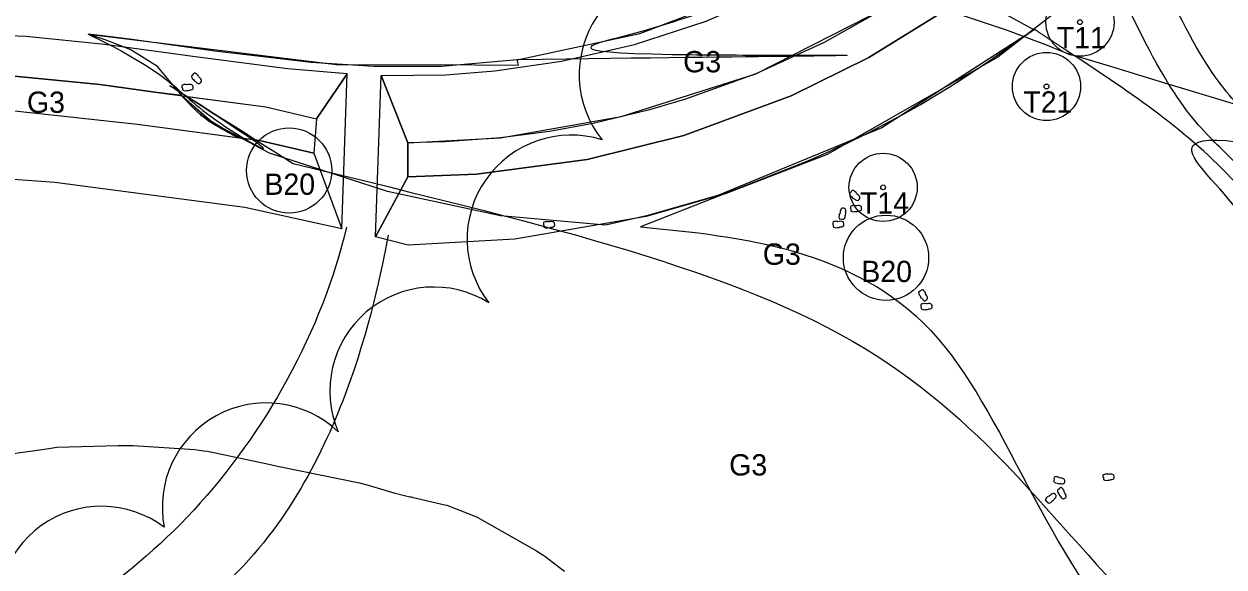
# Model space of a CAD drawing. Extents: x 0 to 512122, y 0 to 6212554.
# Drawn here: x 511431.1 to 511501.5, y 6211428.9 to 6211460.8 of the extents above; entities that cross this region are included whole.
import ezdxf

# ---------------------------------------------------------------- set-up
doc = ezdxf.new("R2010")
doc.units = 0
for name, color, linetype in [('_Marksten', 7, 'Continuous'), ('_Paths', 7, 'Continuous'), ('_Spredmingskorridor', 7, 'Continuous'), ('_Spredmingskorridor_hatch', 7, 'Continuous'), ('Clouds', 7, 'Continuous'), ('L40 jord udlagt muld og grøft', 7, 'Continuous'), ('Skel', 7, 'Continuous'), ('TV_U_AFM_Symbl_Gul', 7, 'Continuous'), ('TV_U_LYS_Mastenummer', 7, 'Continuous'), ('TV_U_LYS_Nyx330-Trafiksti-x2', 7, 'Continuous')]:
    doc.layers.add(name, color=color, linetype=linetype)

# ---------------------------------------------------------------- blocks, each defined once
blk = doc.blocks.new('SOLITAIRE TREES')
at = {"layer": 'Skel'}
for radius in [2, 0.141]:
    blk.add_circle((0, 0), radius, dxfattribs=at)

msp = doc.modelspace()

# ---------------------------------------------------------------- linework, layer by layer
at = {"layer": '_Marksten'}
for points in [[(511440.954, 6211457.714), (511440.981, 6211457.618), (511441.003, 6211457.563), (511441.071, 6211457.512), (511441.11, 6211457.459), (511441.148, 6211457.407), (511441.194, 6211457.399), (511441.225, 6211457.365), (511441.267, 6211457.32), (511441.316, 6211457.292), (511441.393, 6211457.268), (511441.425, 6211457.279), (511441.447, 6211457.297), (511441.481, 6211457.325), (511441.529, 6211457.384), (511441.54, 6211457.432), (511441.533, 6211457.465), (511441.514, 6211457.515), (511441.476, 6211457.575), (511441.418, 6211457.625), (511441.365, 6211457.681), (511441.346, 6211457.749), (511441.294, 6211457.784), (511441.267, 6211457.824), (511441.237, 6211457.852), (511441.17, 6211457.893), (511441.126, 6211457.884), (511441.058, 6211457.831), (511441.033, 6211457.774)], [(511440.419, 6211456.9), (511440.511, 6211456.862), (511440.569, 6211456.845), (511440.651, 6211456.868), (511440.716, 6211456.866), (511440.781, 6211456.864), (511440.815, 6211456.894), (511440.861, 6211456.898), (511440.923, 6211456.903), (511440.975, 6211456.925), (511441.04, 6211456.971), (511441.052, 6211457.003), (511441.052, 6211457.031), (511441.05, 6211457.076), (511441.034, 6211457.15), (511441.002, 6211457.188), (511440.972, 6211457.203), (511440.921, 6211457.218), (511440.85, 6211457.226), (511440.775, 6211457.211), (511440.698, 6211457.203), (511440.633, 6211457.23), (511440.573, 6211457.211), (511440.525, 6211457.213), (511440.485, 6211457.208), (511440.411, 6211457.18), (511440.392, 6211457.14), (511440.392, 6211457.054), (511440.421, 6211456.998)], [(511479.559, 6211450.815), (511479.594, 6211450.722), (511479.622, 6211450.669), (511479.695, 6211450.624), (511479.738, 6211450.576), (511479.781, 6211450.527), (511479.827, 6211450.524), (511479.862, 6211450.493), (511479.908, 6211450.452), (511479.959, 6211450.429), (511480.038, 6211450.413), (511480.069, 6211450.426), (511480.089, 6211450.446), (511480.121, 6211450.478), (511480.163, 6211450.541), (511480.169, 6211450.59), (511480.159, 6211450.622), (511480.135, 6211450.67), (511480.091, 6211450.726), (511480.029, 6211450.771), (511479.971, 6211450.821), (511479.945, 6211450.887), (511479.89, 6211450.917), (511479.859, 6211450.953), (511479.828, 6211450.979), (511479.757, 6211451.014), (511479.714, 6211451), (511479.652, 6211450.941), (511479.631, 6211450.882)], [(511479.213, 6211449.308), (511479.274, 6211449.387), (511479.305, 6211449.438), (511479.305, 6211449.523), (511479.324, 6211449.585), (511479.343, 6211449.647), (511479.323, 6211449.689), (511479.331, 6211449.734), (511479.343, 6211449.795), (511479.335, 6211449.85), (511479.309, 6211449.926), (511479.281, 6211449.946), (511479.253, 6211449.953), (511479.21, 6211449.963), (511479.135, 6211449.967), (511479.09, 6211449.947), (511479.067, 6211449.921), (511479.038, 6211449.876), (511479.013, 6211449.81), (511479.007, 6211449.734), (511478.994, 6211449.658), (511478.951, 6211449.602), (511478.954, 6211449.539), (511478.938, 6211449.494), (511478.933, 6211449.453), (511478.94, 6211449.375), (511478.974, 6211449.345), (511479.057, 6211449.322), (511479.118, 6211449.336)], [(511479.637, 6211449.8), (511479.729, 6211449.762), (511479.787, 6211449.745), (511479.869, 6211449.768), (511479.934, 6211449.766), (511479.999, 6211449.764), (511480.033, 6211449.795), (511480.079, 6211449.798), (511480.141, 6211449.804), (511480.192, 6211449.825), (511480.258, 6211449.871), (511480.27, 6211449.903), (511480.269, 6211449.932), (511480.268, 6211449.976), (511480.251, 6211450.05), (511480.22, 6211450.088), (511480.189, 6211450.103), (511480.139, 6211450.119), (511480.068, 6211450.126), (511479.993, 6211450.111), (511479.916, 6211450.104), (511479.851, 6211450.13), (511479.791, 6211450.111), (511479.743, 6211450.114), (511479.703, 6211450.108), (511479.629, 6211450.08), (511479.609, 6211450.04), (511479.609, 6211449.954), (511479.639, 6211449.899)], [(511461.628, 6211448.857), (511461.72, 6211448.818), (511461.778, 6211448.802), (511461.86, 6211448.824), (511461.925, 6211448.822), (511461.99, 6211448.821), (511462.024, 6211448.851), (511462.07, 6211448.855), (511462.132, 6211448.86), (511462.184, 6211448.882), (511462.249, 6211448.928), (511462.261, 6211448.96), (511462.261, 6211448.988), (511462.259, 6211449.032), (511462.243, 6211449.106), (511462.211, 6211449.145), (511462.181, 6211449.16), (511462.13, 6211449.175), (511462.059, 6211449.182), (511461.984, 6211449.168), (511461.907, 6211449.16), (511461.842, 6211449.187), (511461.782, 6211449.168), (511461.734, 6211449.17), (511461.694, 6211449.165), (511461.62, 6211449.137), (511461.601, 6211449.097), (511461.601, 6211449.011), (511461.63, 6211448.955)], [(511478.596, 6211448.87), (511478.688, 6211448.832), (511478.746, 6211448.815), (511478.828, 6211448.838), (511478.893, 6211448.836), (511478.958, 6211448.834), (511478.993, 6211448.865), (511479.038, 6211448.868), (511479.1, 6211448.873), (511479.152, 6211448.895), (511479.218, 6211448.941), (511479.229, 6211448.973), (511479.229, 6211449.001), (511479.228, 6211449.046), (511479.211, 6211449.12), (511479.179, 6211449.158), (511479.149, 6211449.173), (511479.098, 6211449.188), (511479.027, 6211449.196), (511478.952, 6211449.181), (511478.875, 6211449.173), (511478.81, 6211449.2), (511478.75, 6211449.181), (511478.703, 6211449.183), (511478.662, 6211449.178), (511478.588, 6211449.15), (511478.569, 6211449.11), (511478.569, 6211449.024), (511478.598, 6211448.968)], [(511483.613, 6211445.049), (511483.622, 6211444.95), (511483.634, 6211444.891), (511483.692, 6211444.829), (511483.72, 6211444.77), (511483.749, 6211444.712), (511483.792, 6211444.696), (511483.816, 6211444.657), (511483.85, 6211444.604), (511483.893, 6211444.569), (511483.964, 6211444.531), (511483.998, 6211444.536), (511484.023, 6211444.55), (511484.061, 6211444.571), (511484.119, 6211444.62), (511484.138, 6211444.666), (511484.137, 6211444.7), (511484.128, 6211444.752), (511484.101, 6211444.818), (511484.054, 6211444.878), (511484.011, 6211444.943), (511484.005, 6211445.013), (511483.96, 6211445.057), (511483.941, 6211445.1), (511483.917, 6211445.133), (511483.858, 6211445.186), (511483.813, 6211445.185), (511483.737, 6211445.145), (511483.702, 6211445.093)], [(511483.765, 6211444.054), (511483.857, 6211444.016), (511483.915, 6211444), (511483.997, 6211444.022), (511484.062, 6211444.02), (511484.127, 6211444.018), (511484.161, 6211444.049), (511484.207, 6211444.053), (511484.269, 6211444.058), (511484.32, 6211444.08), (511484.386, 6211444.125), (511484.398, 6211444.157), (511484.397, 6211444.186), (511484.396, 6211444.23), (511484.379, 6211444.304), (511484.348, 6211444.342), (511484.317, 6211444.357), (511484.267, 6211444.373), (511484.196, 6211444.38), (511484.121, 6211444.365), (511484.044, 6211444.358), (511483.979, 6211444.384), (511483.919, 6211444.365), (511483.871, 6211444.368), (511483.831, 6211444.362), (511483.757, 6211444.335), (511483.737, 6211444.294), (511483.737, 6211444.208), (511483.767, 6211444.153)], [(511494.451, 6211434.047), (511494.543, 6211434.009), (511494.6, 6211433.992), (511494.683, 6211434.015), (511494.748, 6211434.013), (511494.813, 6211434.011), (511494.847, 6211434.042), (511494.893, 6211434.045), (511494.954, 6211434.05), (511495.006, 6211434.072), (511495.072, 6211434.118), (511495.084, 6211434.15), (511495.083, 6211434.178), (511495.082, 6211434.223), (511495.065, 6211434.297), (511495.034, 6211434.335), (511495.003, 6211434.35), (511494.952, 6211434.365), (511494.882, 6211434.373), (511494.807, 6211434.358), (511494.73, 6211434.35), (511494.665, 6211434.377), (511494.605, 6211434.358), (511494.557, 6211434.36), (511494.517, 6211434.355), (511494.443, 6211434.327), (511494.423, 6211434.287), (511494.423, 6211434.201), (511494.452, 6211434.146)], [(511491.525, 6211433.946), (511491.6, 6211433.882), (511491.65, 6211433.848), (511491.735, 6211433.844), (511491.797, 6211433.823), (511491.858, 6211433.801), (511491.9, 6211433.82), (511491.945, 6211433.809), (511492.005, 6211433.795), (511492.061, 6211433.8), (511492.138, 6211433.823), (511492.159, 6211433.85), (511492.167, 6211433.878), (511492.179, 6211433.92), (511492.186, 6211433.995), (511492.168, 6211434.041), (511492.143, 6211434.065), (511492.1, 6211434.096), (511492.034, 6211434.124), (511491.959, 6211434.133), (511491.883, 6211434.15), (511491.829, 6211434.195), (511491.767, 6211434.195), (511491.722, 6211434.212), (511491.682, 6211434.219), (511491.603, 6211434.216), (511491.572, 6211434.183), (511491.546, 6211434.101), (511491.556, 6211434.04)], [(511491.21, 6211432.662), (511491.307, 6211432.683), (511491.364, 6211432.701), (511491.419, 6211432.766), (511491.474, 6211432.801), (511491.529, 6211432.836), (511491.54, 6211432.881), (511491.576, 6211432.91), (511491.624, 6211432.949), (511491.654, 6211432.996), (511491.683, 6211433.071), (511491.675, 6211433.104), (511491.658, 6211433.127), (511491.632, 6211433.163), (511491.577, 6211433.215), (511491.529, 6211433.228), (511491.496, 6211433.224), (511491.445, 6211433.208), (511491.382, 6211433.174), (511491.329, 6211433.12), (511491.269, 6211433.07), (511491.2, 6211433.056), (511491.162, 6211433.006), (511491.121, 6211432.981), (511491.091, 6211432.954), (511491.045, 6211432.89), (511491.052, 6211432.845), (511491.1, 6211432.774), (511491.155, 6211432.745)], [(511491.753, 6211433.447), (511491.758, 6211433.347), (511491.768, 6211433.288), (511491.823, 6211433.224), (511491.849, 6211433.164), (511491.876, 6211433.105), (511491.918, 6211433.087), (511491.941, 6211433.047), (511491.972, 6211432.994), (511492.014, 6211432.957), (511492.084, 6211432.917), (511492.118, 6211432.92), (511492.143, 6211432.933), (511492.183, 6211432.953), (511492.242, 6211433), (511492.263, 6211433.045), (511492.264, 6211433.079), (511492.256, 6211433.131), (511492.232, 6211433.198), (511492.186, 6211433.26), (511492.147, 6211433.326), (511492.143, 6211433.396), (511492.099, 6211433.442), (511492.081, 6211433.486), (511492.059, 6211433.52), (511492.002, 6211433.575), (511491.957, 6211433.575), (511491.88, 6211433.538), (511491.842, 6211433.488)]]:
    msp.add_lwpolyline(points, close=True, dxfattribs=at)
at = {"layer": '_Paths'}
for points in [[(511619.187, 6211386.799), (511596.582, 6211393.479), (511585.389, 6211391.465), (511574.074, 6211393.08), (511564.353, 6211396.519), (511555.151, 6211400.37), (511543.395, 6211408.318), (511538.005, 6211417.069), (511534.527, 6211422.707), (511527.544, 6211428.597), (511520.899, 6211430.592), (511516.505, 6211433.059), (511513.01, 6211439.693), (511510.466, 6211444.112), (511507.781, 6211450.658), (511503.375, 6211454.994), (511500.203, 6211458.077), (511497.377, 6211464.569)], [(511614.911, 6211385.469), (511596.457, 6211390.915), (511585.439, 6211388.932), (511573.475, 6211390.64), (511563.453, 6211394.185), (511553.957, 6211398.16), (511541.549, 6211406.549), (511535.876, 6211415.757), (511532.609, 6211421.054), (511526.328, 6211426.352), (511519.916, 6211428.277), (511514.638, 6211431.24), (511510.82, 6211438.486), (511508.216, 6211443.009), (511505.662, 6211449.236), (511501.627, 6211453.206), (511498.108, 6211456.628), (511495.085, 6211463.571)], [(511450.039, 6211448.86), (511448.659, 6211442.81), (511441.758, 6211430.614), (511427.385, 6211422.182), (511415.868, 6211415.798), (511410.87, 6211405.413), (511411.537, 6211394.313), (511413.909, 6211386.762), (511418.057, 6211376.543), (511422.936, 6211366.106), (511450.039, 6211448.86), (511422.936, 6211366.106)], [(511452.493, 6211448.381), (511452.097, 6211446.356), (511450.738, 6211439.396), (511444.066, 6211426.759), (511429.553, 6211420.175), (511417.018, 6211415.504), (511412.404, 6211405.178), (511413.418, 6211395.795), (511416.522, 6211386.629), (511420.496, 6211376.909), (511423.945, 6211369.766), (511425.261, 6211367.041)]]:
    msp.add_open_spline(points, degree=3, dxfattribs=at)
at = {"layer": '_Spredmingskorridor'}
msp.add_lwpolyline([(511460.05, 6211458.675), (511455.629, 6211458.284), (511451.659, 6211458.278), (511447.984, 6211458.509), (511442.319, 6211459.181), (511437.483, 6211459.853), (511435.598, 6211460.091), (511434.899, 6211460.179)], dxfattribs=at)
for points in [[(511492.266, 6211459.065), (511479.169, 6211464.34), (511471.697, 6211461.691), (511466.477, 6211459.966), (511460.05, 6211458.675), (511492.266, 6211459.065), (511460.05, 6211458.675)], [(511434.899, 6211460.179), (511438.972, 6211458.194), (511440.607, 6211456.317), (511444.33, 6211453.77), (511446.919, 6211452.593), (511434.899, 6211460.179), (511446.919, 6211452.593)], [(511618.625, 6211420.62), (511606.029, 6211410.569), (511596.93, 6211398.178), (511583.32, 6211390.017), (511570.813, 6211390.175), (511555.007, 6211396.479), (511539.801, 6211408.822), (511527.664, 6211423.862), (511513.195, 6211431.425), (511508.403, 6211440.656), (511501.753, 6211451.707), (511492.266, 6211459.065), (511618.625, 6211420.62), (511492.266, 6211459.065)], [(511446.919, 6211452.593), (511459.024, 6211449.612), (511483.052, 6211444.239), (511494.738, 6211426.247), (511517.996, 6211408.457), (511535.129, 6211387.296), (511545.806, 6211384.873), (511574.749, 6211382.071), (511593.151, 6211386.596), (511609.301, 6211398.194), (511446.919, 6211452.593), (511609.301, 6211398.194)]]:
    msp.add_open_spline(points, degree=3, dxfattribs=at)
at = {"layer": '_Spredmingskorridor_hatch'}
msp.add_lwpolyline([(511434.899, 6211460.179), (511449.469, 6211458.386), (511457.611, 6211458.367), (511460.142, 6211458.361), (511460.05, 6211458.675), (511467.249, 6211460.221), (511475.684, 6211463.431), (511478.446, 6211464.171), (511483.675, 6211464.122), (511490.383, 6211460.419), (511481.456, 6211454.685), (511471.837, 6211450.715), (511467.654, 6211449.509), (511465.235, 6211448.962), (511459.073, 6211449.517), (511452.451, 6211450.939), (511445.522, 6211453.191), (511442.233, 6211454.953), (511440.542, 6211456.402), (511439.749, 6211457.341), (511438.957, 6211458.281), (511437.872, 6211458.962), (511437.365, 6211459.28), (511435.882, 6211459.843)], close=True, dxfattribs=at)
msp.add_lwpolyline([(511490.402, 6211460.453), (511487.796, 6211458.617), (511487.477, 6211458.398), (511487.03, 6211458.097), (511486.795, 6211457.941), (511485.779, 6211457.284), (511485.409, 6211457.052), (511484.751, 6211456.649), (511483.711, 6211456.034), (511483.288, 6211455.792), (511482.658, 6211455.44), (511481.594, 6211454.867), (511481.117, 6211454.619), (511480.518, 6211454.315), (511479.432, 6211453.786), (511479.066, 6211453.613), (511478.9, 6211453.536), (511478.335, 6211453.278), (511477.228, 6211452.792), (511476.64, 6211452.544), (511476.112, 6211452.328), (511467.291, 6211448.868)], dxfattribs=at)
for points, degree in [([(511492.308, 6211459.197), (511491.673, 6211459.619), (511491.038, 6211460.041), (511490.402, 6211460.453)], 2), ([(511581.75, 6211389.913), (511577.7, 6211389.37), (511567.855, 6211390.317), (511554.005, 6211396.469), (511538.606, 6211407.597), (511530.73, 6211425.908), (511512.751, 6211428.394), (511508.404, 6211441.832), (511502.763, 6211452.312), (511495.709, 6211456.958), (511492.308, 6211459.197)], 3), ([(511467.291, 6211448.868), (511473.268, 6211448.326), (511486.519, 6211446.703), (511493.234, 6211420.769), (511520.952, 6211413.243), (511528.733, 6211386.924), (511552.285, 6211384.428), (511571.21, 6211380.366), (511589.487, 6211384.409), (511596.578, 6211388.532), (511598.184, 6211389.583)], 3)]:
    msp.add_open_spline(points, degree=degree, dxfattribs=at)
at = {"layer": 'Clouds'}
for centre, start, end in [((511469.797, 6211457.789), 73.7112, 218.7112), ((511463.223, 6211448.15), 72.7062, 217.7062), ((511455.168, 6211439.243), 58.03884, 203.03884), ((511445.34, 6211432.445), 46.30662, 191.30662), ((511435.682, 6211426.381), 52.94082, 197.94082)]:
    msp.add_arc(centre, 6.1, start, end, dxfattribs=at)
at = {"layer": 'L40 jord udlagt muld og grøft'}
for points in [[(511452.089, 6211457.757), (511455.883, 6211457.797), (511458.754, 6211458.017), (511462.669, 6211458.587), (511466.946, 6211459.576), (511471.14, 6211460.94), (511476.281, 6211463.197), (511480.272, 6211465.454), (511484.554, 6211468.459), (511487.69, 6211471.125), (511489.2, 6211467.192), (511487.305, 6211465.616), (511484.793, 6211463.737), (511481.902, 6211461.832), (511478.062, 6211459.686), (511474.061, 6211457.856), (511469.926, 6211456.355), (511467.817, 6211455.732), (511464.514, 6211454.937), (511461.957, 6211454.47), (511459.08, 6211454.092), (511455.823, 6211453.851), (511453.649, 6211453.799)], [(511489.2, 6211467.192), (511490.613, 6211465.77), (511485.335, 6211461.675), (511480.685, 6211458.81), (511476.131, 6211456.564), (511469.835, 6211454.235), (511464.172, 6211452.828), (511457.679, 6211451.96), (511453.654, 6211451.799), (511453.649, 6211453.799), (511459.08, 6211454.092), (511466.165, 6211455.334), (511474.061, 6211457.856), (511481.902, 6211461.832), (511484.793, 6211463.737)], [(511490.613, 6211465.77), (511494.758, 6211464.022), (511492.715, 6211462.301), (511488.249, 6211458.832), (511478.239, 6211453.123), (511472.318, 6211450.824), (511467.621, 6211449.487), (511459.919, 6211448.147), (511453.669, 6211447.799), (511451.752, 6211448.284), (511453.654, 6211451.799), (511457.679, 6211451.96), (511464.172, 6211452.828), (511469.835, 6211454.235), (511476.131, 6211456.564), (511480.685, 6211458.81), (511485.335, 6211461.675)], [(511448.281, 6211455.2), (511450.091, 6211457.845), (511446.592, 6211458.144), (511441.032, 6211458.856), (511435.871, 6211459.561), (511431.226, 6211460.037), (511427.363, 6211460.201), (511423.803, 6211460.095), (511419.987, 6211459.694), (511417.262, 6211459.221), (511412.63, 6211458.047), (511411.501, 6211457.69), (511413.925, 6211455.968), (511418.034, 6211456.964), (511421.527, 6211457.51), (511424.901, 6211457.788), (511430.573, 6211457.715), (511435.577, 6211457.214), (511438.812, 6211456.779), (511445.318, 6211455.907)], [(511448.281, 6211455.2), (511448.134, 6211453.202), (511449.767, 6211448.758), (511450.091, 6211457.845)], [(511452.089, 6211457.757), (511453.649, 6211453.799), (511453.654, 6211451.799), (511451.752, 6211448.284)], [(511445.318, 6211455.907), (511448.281, 6211455.2), (511448.134, 6211453.202), (511444.951, 6211453.937), (511443.699, 6211454.09), (511441.926, 6211455.166), (511440.396, 6211456.557)], [(511449.767, 6211448.758), (511444.09, 6211450.012), (511432.94, 6211451.482), (511428.082, 6211451.824), (511421.542, 6211451.463), (511414.315, 6211449.849), (511414.602, 6211454.082), (511421.762, 6211455.523), (511425.895, 6211455.823), (511430.043, 6211455.743), (511437.787, 6211454.903), (511444.951, 6211453.937), (511448.134, 6211453.202)]]:
    msp.add_lwpolyline(points, close=True, dxfattribs=at)
for points in [[(511490.613, 6211465.77), (511494.758, 6211464.022), (511492.715, 6211462.301), (511488.249, 6211458.832), (511478.239, 6211453.123), (511472.318, 6211450.824), (511467.621, 6211449.487), (511459.919, 6211448.147), (511453.669, 6211447.799), (511451.752, 6211448.284), (511453.654, 6211451.799), (511457.679, 6211451.96), (511464.172, 6211452.828), (511469.835, 6211454.235), (511476.131, 6211456.564), (511480.685, 6211458.81), (511485.335, 6211461.675), (511490.613, 6211465.77)], [(511440.382, 6211456.569), (511438.812, 6211456.779), (511435.577, 6211457.214), (511430.573, 6211457.715), (511424.901, 6211457.788), (511421.527, 6211457.51), (511418.034, 6211456.964), (511413.925, 6211455.968), (511414.602, 6211454.082), (511421.762, 6211455.523), (511425.895, 6211455.823), (511430.043, 6211455.743), (511437.787, 6211454.903), (511443.659, 6211454.111)], [(511440.392, 6211456.557), (511445.318, 6211455.907), (511448.281, 6211455.2), (511448.134, 6211453.202), (511444.951, 6211453.937), (511443.699, 6211454.09), (511441.926, 6211455.166), (511440.382, 6211456.569)]]:
    msp.add_lwpolyline(points, dxfattribs=at)
for points in [[(511440.607, 6211456.317), (511440.531, 6211456.399), (511440.456, 6211456.483), (511440.382, 6211456.569)], [(511443.659, 6211454.111), (511442.537, 6211454.702), (511441.464, 6211455.393), (511440.607, 6211456.317)]]:
    msp.add_open_spline(points, degree=2, dxfattribs=at)
at = {"layer": 'TV_U_LYS_Mastenummer'}
for centre in [(511446.683, 6211452.176), (511446.683, 6211452.176), (511481.698, 6211447.059), (511481.698, 6211447.059)]:
    msp.add_circle(centre, 2.5, dxfattribs=at)
at = {"layer": 'TV_U_LYS_Nyx330-Trafiksti-x2'}
msp.add_lwpolyline([(511428.555, 6211435.3), (511432.576, 6211435.879), (511433.054, 6211435.957), (511436.653, 6211436.054), (511437.169, 6211436.048), (511437.528, 6211436.052), (511441.142, 6211435.802), (511441.658, 6211435.732), (511441.887, 6211435.705), (511445.49, 6211434.95), (511445.997, 6211434.834), (511446.093, 6211434.814), (511450.802, 6211433.848), (511451.328, 6211433.714), (511452.827, 6211433.278), (511452.889, 6211433.26), (511452.89, 6211433.26), (511453.055, 6211433.219), (511453.761, 6211433.043), (511453.838, 6211433.026), (511453.968, 6211432.997), (511455.822, 6211432.575), (511455.932, 6211432.544), (511457.389, 6211431.97), (511457.706, 6211431.848), (511461.19, 6211429.864), (511461.622, 6211429.593), (511461.677, 6211429.551), (511462.448, 6211428.961), (511462.841, 6211428.68)], dxfattribs=at)

# ---------------------------------------------------------------- block references
at = {"layer": 'Skel'}
for p in [(511493.074, 6211460.876), (511491.112, 6211457.106), (511481.526, 6211451.186)]:
    msp.add_blockref('SOLITAIRE TREES', p, dxfattribs=at)

# ---------------------------------------------------------------- texts
at = {"layer": 'TV_U_AFM_Symbl_Gul'}
for s, p in [('T11', (511491.717, 6211459.341)), ('G3', (511469.797, 6211457.933)), ('T21', (511489.755, 6211455.571)), ('G3', (511431.301, 6211455.555)), ('B20', (511445.232, 6211450.749)), ('T14', (511480.169, 6211449.651)), ('G3', (511474.471, 6211446.646)), ('B20', (511480.248, 6211445.631)), ('G3', (511472.498, 6211434.286))]:
    msp.add_text(s, height=1.25, dxfattribs=at).set_placement(p)

doc.saveas('drawing.dxf')
